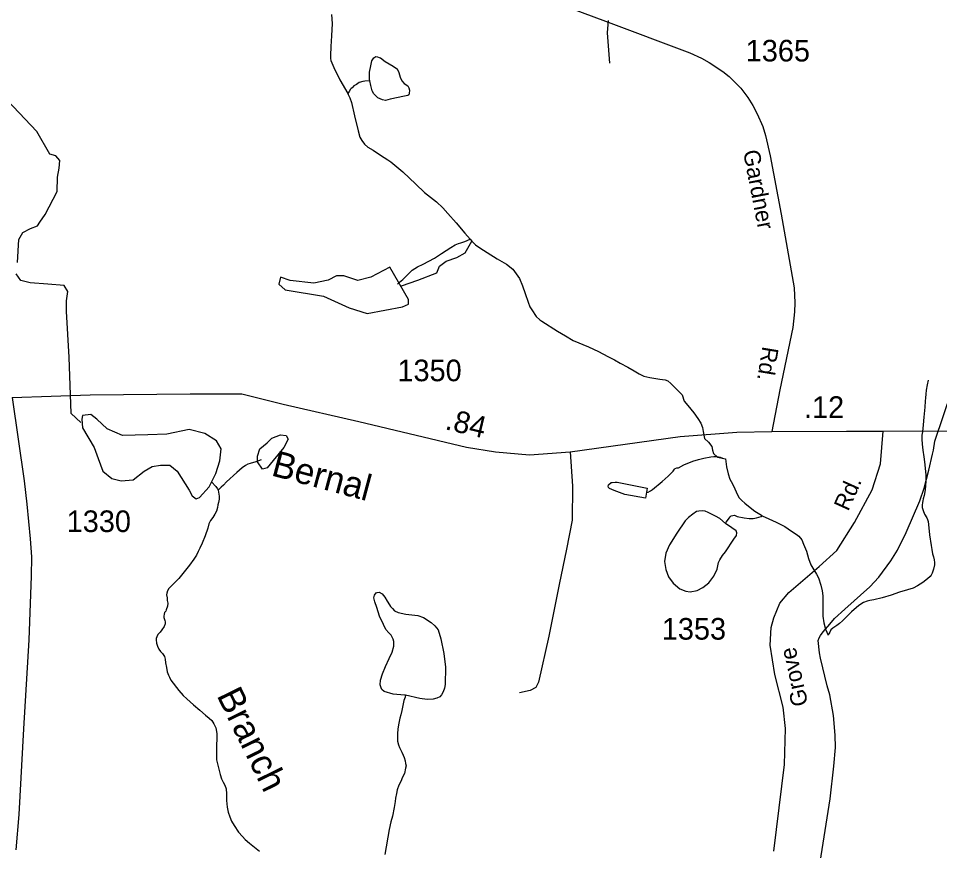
# Model space of a CAD drawing. Extents: x 2082433 to 2279600, y 546599 to 755198.
# Drawn here: x 2148448 to 2153778, y 616395 to 621207 of the extents above; entities that cross this region are included whole.
import ezdxf

# ---------------------------------------------------------------- set-up
doc = ezdxf.new("R2010")
doc.units = 0
for name, color, linetype in [('Exist Boundary Political Fire Districts', 7, 'Continuous'), ('Exist Hydrographic Creek Single Shore', 7, 'Continuous'), ('Exist Hydrographic Creek Single Shore Label', 7, 'Continuous'), ('Exist Hydrographic Misc Water Feature', 7, 'Continuous'), ('Exist Hydrographic Pond Over 1500 Sq Ft', 7, 'Continuous'), ('Exist Road Non-System Type 51', 7, 'Continuous'), ('Exist Road Secondary Mileage Hundredths English Label', 7, 'Continuous'), ('Exist Road Secondary Type 51 Attributed', 7, 'Continuous'), ('Exist Road Secondary Type 51 Label', 7, 'Continuous'), ('Exist Road Secondary Type 51 Number Label', 7, 'Continuous')]:
    doc.layers.add(name, color=color, linetype=linetype)

msp = doc.modelspace()

# ---------------------------------------------------------------- linework, layer by layer
at = {"layer": 'Exist Boundary Political Fire Districts'}
msp.add_lwpolyline([(2153087.7, 616327.6), (2153144.5, 616694.2), (2153165.6, 616882.9), (2153175, 616991.3), (2153173.8, 617061.5), (2153164.8, 617175.4), (2153143, 617295.8), (2153127.3, 617347.8), (2153088.3, 617506.9), (2153082.6, 617538.6), (2153075, 617609.9), (2153080.3, 617625.6), (2153088.3, 617638.8), (2153104.1, 617659.9), (2153142.2, 617704.7), (2153169.9, 617737.6), (2153229, 617790), (2153375.2, 617919.8), (2153426, 617975.8), (2153496.3, 618070.4), (2153534.9, 618132.7), (2153584.3, 618234), (2153663.7, 618416.5), (2153689.5, 618491.2), (2153715.5, 618594.3), (2153736.3, 618686.3), (2153741.8, 618710.3), (2153751.2, 618762.9), (2155677.9, 624465.5)], dxfattribs=at)
at = {"layer": 'Exist Hydrographic Creek Single Shore'}
for points in [[(2150258.8, 621229.1), (2150262.7, 621177), (2150259.2, 621107), (2150255.7, 621045), (2150253.9, 620993), (2150253.9, 620975.2), (2150255.9, 620963.1), (2150272.3, 620923.3), (2150308.8, 620851.3), (2150353.3, 620773.6)], [(2148442.2, 619795.2), (2148450.2, 619929.5), (2148473.1, 619969.9), (2148517.5, 619992.8), (2148559.3, 620007.6), (2148572.8, 620029.2), (2148602.4, 620073.6), (2148672.4, 620207), (2148673.8, 620289.2), (2148683.2, 620340.4), (2148687.3, 620384.8), (2148665.7, 620411.8), (2148629.3, 620421.2), (2148555.2, 620554), (2148313.3, 620804.9)], [(2150353.3, 620773.6), (2150357, 620767.8), (2150365, 620747.9), (2150375.3, 620720), (2150392.1, 620644), (2150414.4, 620556.3), (2150424.1, 620520.4), (2150434.3, 620500.2), (2150450.5, 620480.3), (2150469, 620462.5), (2150500.7, 620444.7), (2150543.2, 620416.8), (2150585, 620389), (2150603.1, 620377.3), (2150671.6, 620319.5), (2150747.6, 620247.9), (2150797.9, 620200.2), (2150866.4, 620146.9), (2150904.7, 620111.1), (2150933, 620079.2), (2150981.4, 620025.3), (2151031.4, 619965.8), (2151061.6, 619930)], [(2150664.8, 619660.7), (2150759.4, 619693.1), (2150868.9, 619735.4), (2150883.8, 619775.2), (2150923.6, 619802.6), (2150985.8, 619825), (2151033.1, 619852.4), (2151071.4, 619918)], [(2151061.6, 619930), (2151071.4, 619918), (2151093.5, 619898), (2151117.7, 619880.1), (2151160, 619852.7), (2151218.2, 619816.7), (2151272.4, 619785.4), (2151308.6, 619757.2), (2151328.5, 619729.4), (2151346.8, 619703.5), (2151365, 619659.8), (2151379.4, 619615.9), (2151397.8, 619566), (2151407.5, 619539.9), (2151425.9, 619510.3), (2151435.6, 619494.2), (2151443.8, 619484.1), (2151464.3, 619464.3), (2151476.2, 619456.5), (2151566.4, 619399), (2151614.4, 619371.1), (2151658.7, 619345.4), (2151746.8, 619308.1), (2151805.1, 619280.2), (2151859, 619252.6), (2151897.1, 619233), (2151929.5, 619213.2), (2151973.6, 619189.4), (2152011.4, 619169.5), (2152039.5, 619151.9), (2152067.3, 619138), (2152101.8, 619129.9), (2152159.6, 619120.3), (2152189.6, 619116.6), (2152206.2, 619110.5), (2152223.8, 619096.8), (2152248.4, 619070.8), (2152288, 619031.2), (2152300.1, 618993.3), (2152322.2, 618968.2), (2152355.4, 618926.9), (2152380, 618893.8), (2152396.6, 618866.1), (2152407.2, 618842), (2152409.2, 618818.9), (2152418.2, 618777.7), (2152440.8, 618757.1), (2152459.9, 618731.5), (2152464.5, 618710.9), (2152469.5, 618690.3), (2152492.1, 618669.7), (2152540, 618660.5)], [(2148810.1, 618870.1), (2148754.3, 618922.8), (2148741, 619247.6), (2148726, 619511.4), (2148726, 619573.6), (2148733.5, 619628.4), (2148713.6, 619663.2), (2148619, 619670.7), (2148517, 619678.1), (2148462.2, 619690.6), (2148434.8, 619730.4)], [(2149853, 618653.6), (2149821, 618643.4), (2149789.6, 618633.1), (2149775.3, 618629.2), (2149761.3, 618621.2), (2149743.1, 618608.9), (2149711.7, 618580.8), (2149652, 618526.6), (2149634, 618508.2), (2149622.3, 618496.2), (2149607.9, 618482.1), (2149604.5, 618478.2)], [(2152540, 618660.5), (2152544.3, 618614.9), (2152554.8, 618572.7), (2152564.6, 618542.8), (2152579.2, 618515.1), (2152593.1, 618487), (2152609.3, 618451.3), (2152619.3, 618435.2), (2152633.7, 618419.2), (2152651.3, 618403.2), (2152681.5, 618379.6), (2152709.8, 618357.9), (2152747.9, 618333.8), (2152751.8, 618330)], [(2149565.6, 618526.7), (2149590.3, 618500.2), (2149600.2, 618486.1), (2149604.5, 618478.2)], [(2149604.5, 618478.2), (2149606.1, 618468.3), (2149610.2, 618444.1), (2149610.6, 618426.2), (2149606.3, 618408.2), (2149602.8, 618394.1), (2149601, 618378.2), (2149594.6, 618358), (2149584.8, 618340), (2149573.3, 618321.9), (2149559.3, 618304.2), (2149549.1, 618284.2), (2149543.4, 618259.9), (2149529.6, 618215.8), (2149512.2, 618171.8), (2149498, 618143.9), (2149488.4, 618123.5), (2149478.1, 618103.5), (2149462.8, 618079.5), (2149438.4, 618045.4), (2149377.3, 617969.2), (2149337.3, 617928.9), (2149319.4, 617911), (2149311.6, 617896.7), (2149307.5, 617882.7), (2149305.3, 617874.6), (2149308, 617856.7), (2149309.8, 617840.6), (2149311.9, 617824.9), (2149310.2, 617809), (2149303.9, 617786.8), (2149300.4, 617778.8), (2149294.4, 617770.8), (2149292.2, 617762.6), (2149290.3, 617750.7), (2149290.1, 617742.6), (2149294.8, 617724.9), (2149296.5, 617716.9), (2149296.5, 617706.8), (2149290.9, 617690.6), (2149279, 617670.5), (2149269, 617658.7), (2149255.1, 617644.5), (2149248.9, 617630.4), (2149245.2, 617620.5), (2149245, 617614.4), (2149247.3, 617594.6), (2149253.6, 617576.6), (2149261.6, 617558.7), (2149269.4, 617546.6), (2149281.5, 617534.6), (2149285.6, 617528.8), (2149293.8, 617517), (2149297.9, 617501), (2149299.8, 617480.8), (2149304.1, 617453), (2149308.4, 617428.8), (2149316.2, 617409), (2149322.3, 617397.1), (2149330.7, 617381.2), (2149376.9, 617321.1), (2149400.8, 617291.6), (2149423, 617271.6), (2149461.5, 617237.7), (2149497, 617206), (2149529.8, 617178.4), (2149551.6, 617160.5), (2149568, 617146.6), (2149579.6, 617128.6), (2149589.9, 617104.8), (2149595.8, 617072.6), (2149596.3, 617038.5), (2149594.6, 617006.7), (2149594.6, 616980.8), (2149594.8, 616964.5), (2149595, 616944.6), (2149595, 616918.7), (2149597.3, 616904.5), (2149605.1, 616872.9), (2149615.3, 616834.9), (2149623.3, 616808.9), (2149633.6, 616791.2), (2149641.6, 616772.9), (2149649.8, 616751), (2149652, 616723.1), (2149652, 616685), (2149656.3, 616645), (2149662.5, 616617.3), (2149670.9, 616589.2), (2149680.5, 616565.5), (2149697.1, 616539.4), (2149721.3, 616501.7), (2149745.1, 616475.8), (2149759.5, 616459.9), (2149785.5, 616438.1), (2149803.8, 616421.9), (2149824.1, 616406.3), (2149844, 616392.4)], [(2152751.8, 618330), (2152789.9, 618314.1), (2152832.2, 618294.3), (2152882.4, 618268.9), (2152920.6, 618242.8), (2152948.7, 618225.2), (2152964.4, 618213.5), (2152980.8, 618191.2), (2152990.9, 618167.3), (2153007.3, 618125.5), (2153019.4, 618083.5), (2153033.3, 618047.7), (2153049.5, 618017.7), (2153066.1, 617993.8), (2153077.8, 617972.1), (2153090.3, 617930), (2153098.1, 617896), (2153102.4, 617868.2), (2153102.6, 617790.3), (2153103.3, 617750.1), (2153109.2, 617712.2), (2153117.6, 617676.1), (2153133.4, 617640.5)], [(2150688.4, 617292.7), (2150686.3, 617282.9), (2150678.7, 617262.5), (2150672.8, 617234.7), (2150667, 617204.7), (2150661.3, 617180.4), (2150655.4, 617160.6), (2150649.4, 617132.3), (2150643.9, 617098.7), (2150641.6, 617070.7), (2150641.8, 617046.7), (2150641.8, 617028.4), (2150648, 617006.4), (2150654.1, 616990.5), (2150666.4, 616964.7), (2150674.6, 616946.9), (2150680.8, 616932.9), (2150686.3, 616913), (2150688.8, 616898.9), (2150691, 616884.7), (2150688.8, 616870.9), (2150681.2, 616840.8), (2150669.1, 616814.7), (2150663.6, 616798.9), (2150649.4, 616772.6), (2150639.6, 616746.5), (2150635.9, 616724.8), (2150629.7, 616698.5), (2150628.1, 616678.5), (2150622.1, 616644.5), (2150612.5, 616594.5), (2150602.7, 616560.7), (2150592.6, 616516.4), (2150567.8, 616372.5)]]:
    msp.add_lwpolyline(points, dxfattribs=at)
at = {"layer": 'Exist Hydrographic Misc Water Feature'}
for points in [[(2150480.6, 620846.4), (2150478.8, 620856.4), (2150480.4, 620896.3), (2150486.4, 620932.3), (2150494, 620962.4), (2150503.8, 620978.3), (2150515.9, 620986.7), (2150525.8, 620984.8), (2150535.6, 620980.8), (2150543.8, 620978.8), (2150569.8, 620958.6), (2150616.2, 620930.9), (2150636.1, 620917.4), (2150640.4, 620915.1), (2150648.6, 620895.2), (2150656.2, 620867.3), (2150666.6, 620845.4), (2150680.4, 620831.6), (2150700.7, 620817.6), (2150706.6, 620805.7), (2150710.7, 620791.7), (2150709.1, 620773.7), (2150706.8, 620765.6), (2150701.1, 620761.6), (2150682.8, 620757.4), (2150599.2, 620739.3), (2150573.1, 620733.1), (2150555.1, 620737), (2150527.2, 620748.5), (2150504.8, 620770.5), (2150494.6, 620788.3), (2150487, 620818.3), (2150480.6, 620846.4)], [(2150480.6, 620846.4), (2150452.6, 620844.1), (2150440.7, 620842.3), (2150420.6, 620836), (2150404.8, 620825.8), (2150388.6, 620817.7), (2150378.5, 620805.8), (2150372.8, 620801.8), (2150368.7, 620797.6), (2150361.3, 620783.7), (2150353.3, 620773.6)], [(2150641, 619669.5), (2150652.9, 619681.5), (2150673, 619697.9), (2150692.9, 619718), (2150708.9, 619733.9), (2150726.3, 619750.3), (2150756.4, 619770.5), (2150790.3, 619786.5), (2150856.3, 619820.7), (2150895.9, 619847.2), (2150950, 619883.2), (2150975.8, 619897.6), (2150993.7, 619905.4), (2151007.6, 619909.8), (2151031.4, 619917.9), (2151061.6, 619930)], [(2153711.4, 619115.2), (2153705.5, 619089), (2153699.8, 619057), (2153697.7, 619035), (2153695.7, 619013), (2153693.6, 618993), (2153692.4, 618959.1), (2153686.4, 618901.3), (2153682.5, 618857.2), (2153678.8, 618816.8), (2153675.2, 618797.1), (2153675.4, 618773.2), (2153677.4, 618745.2), (2153681.5, 618711), (2153686, 618671), (2153689.9, 618643.2), (2153692.4, 618625), (2153698.5, 618565.2), (2153698.3, 618531.2), (2153694.8, 618481.5), (2153688.9, 618449.1), (2153683.2, 618429.3), (2153681.1, 618417), (2153679.1, 618407.2), (2153677.6, 618393.2), (2153677.2, 618379.1), (2153683.6, 618361.1), (2153691.4, 618341.2), (2153703.5, 618319.5), (2153707.8, 618309.6), (2153709.8, 618303.6), (2153711.7, 618297.2), (2153716.4, 618261.3), (2153720.3, 618221.7), (2153728.7, 618159.6), (2153732.8, 618135.5), (2153736.9, 618111.7), (2153742.8, 618093.8), (2153747.1, 618075.7), (2153749.4, 618061.6), (2153749.2, 618047.8), (2153743.4, 618021.5), (2153735.6, 617999.6), (2153729.7, 617987.5), (2153723.3, 617979.5), (2153707.3, 617965.7), (2153681.9, 617945.2), (2153650.1, 617925.3), (2153625.9, 617913.1), (2153591.9, 617902.9), (2153546.2, 617888.7), (2153498.6, 617872.4), (2153446.5, 617855.9), (2153398.3, 617845.8), (2153374.3, 617841.7), (2153358.3, 617837.6), (2153338.7, 617829.2), (2153310.6, 617811.2), (2153268.9, 617774.9), (2153243.1, 617750.8), (2153226.9, 617735), (2153215.6, 617722.9), (2153199.6, 617708.7), (2153183.6, 617696.5), (2153171.1, 617688.7), (2153159.7, 617680.7), (2153149.4, 617670.5), (2153143.7, 617658.4), (2153137.7, 617648.3), (2153133.4, 617640.5)], [(2152081.3, 618468.3), (2152091.3, 618468.4), (2152105.3, 618474.4), (2152117.6, 618482.3), (2152173.4, 618528.6), (2152206.8, 618560.8), (2152236.5, 618588.8), (2152244.5, 618601), (2152248.6, 618605.2), (2152258.4, 618609), (2152266.7, 618609), (2152298.2, 618625.3), (2152350.5, 618645.8), (2152382.3, 618656), (2152413.9, 618664.2), (2152454.1, 618672.3), (2152472.1, 618674.4), (2152490, 618674.6), (2152508, 618670.6), (2152521.9, 618664.5), (2152540, 618660.5)], [(2152081.3, 618468.3), (2152075.5, 618432.3), (2151957.6, 618453.3), (2151895.3, 618477), (2151867.4, 618488.9), (2151863.3, 618494.8), (2151861.3, 618502.8), (2151863.1, 618509), (2151877.1, 618523.1), (2151883, 618523.1), (2151901, 618525.2), (2151913.1, 618525.4), (2151979.2, 618511.7), (2152085.4, 618490.4), (2152081.3, 618468.3)], [(2152540.2, 618287), (2152506.2, 618314.4), (2152482.2, 618328.6), (2152439.9, 618350.4), (2152422.1, 618358), (2152405.7, 618360), (2152385.8, 618357.8), (2152371.8, 618355.8), (2152350.1, 618339.6), (2152326.1, 618321.4), (2152306.4, 618301.6), (2152256.8, 618231.3), (2152215.2, 618162.9), (2152193.7, 618115.1), (2152185.7, 618066.9), (2152193.7, 618021), (2152210.3, 617977.2), (2152236.1, 617941.2), (2152274.6, 617909.4), (2152310.5, 617895.5), (2152334.5, 617891.8), (2152374.7, 617898), (2152408.3, 617916.4), (2152442.4, 617942.4), (2152472.1, 617982.6), (2152492, 618022.6), (2152495.7, 618040.6), (2152499.6, 618060.8), (2152505.7, 618076.9), (2152521.5, 618100.8), (2152539.2, 618122.9), (2152586.9, 618195.1), (2152602.5, 618217.1), (2152604.4, 618233.1), (2152600.5, 618243.4), (2152576.3, 618260.8), (2152540.2, 618287)], [(2152540.2, 618287), (2152544.1, 618294.9), (2152550, 618302.9), (2152560.1, 618316.8), (2152566, 618324.8), (2152572.2, 618331.2), (2152581.8, 618333), (2152592.1, 618335.1), (2152606, 618327.3), (2152646.4, 618319.2), (2152676.3, 618315.5), (2152700.1, 618315.5), (2152718.2, 618319.7), (2152746.1, 618326), (2152751.8, 618330)]]:
    msp.add_lwpolyline(points, dxfattribs=at)
at = {"layer": 'Exist Hydrographic Pond Over 1500 Sq Ft'}
for points in [[(2149964.2, 619710.5), (2149954.2, 619670.7), (2149991.6, 619638.3), (2150213.1, 619601), (2150362.4, 619533.8), (2150466.9, 619501.4), (2150671, 619538.8), (2150705.9, 619553.7), (2150705.9, 619581.1), (2150596.4, 619767.7), (2150486.8, 619710.5), (2150412.2, 619690.6), (2150330.1, 619718), (2150287.7, 619718), (2150240.5, 619693.1), (2150158.3, 619675.7), (2150021.4, 619690.6)], [(2148866.6, 618916.6), (2148819.3, 618911.6), (2148814.4, 618889.2), (2148819.3, 618839.4), (2148886.5, 618724.9), (2148908.9, 618662.7), (2148936.3, 618588), (2148988.6, 618545.7), (2149043.3, 618533.3), (2149113, 618538.3), (2149175.2, 618588), (2149222.5, 618615.4), (2149269.8, 618622.9), (2149324.6, 618622.9), (2149366.9, 618588), (2149436.6, 618478.5), (2149454, 618446.2), (2149476.4, 618428.8), (2149496.3, 618436.2), (2149551.1, 618498.5), (2149590.9, 618575.6), (2149613.3, 618647.8), (2149620.7, 618717.5), (2149593.4, 618764.8), (2149526.2, 618807.1), (2149436.6, 618829.5), (2149307.2, 618802.1), (2149197.6, 618799.6), (2149050.8, 618794.6), (2148961.2, 618834.4), (2148901.5, 618889.2)], [(2149964.2, 618799.6), (2149996.6, 618794.6), (2150009, 618774.7), (2149984.1, 618724.9), (2149887, 618608), (2149859.7, 618600.5), (2149832.3, 618642.8), (2149832.3, 618675.2), (2149844.7, 618717.5), (2149887, 618752.3), (2149914.4, 618779.7)]]:
    msp.add_lwpolyline(points, close=True, dxfattribs=at)
msp.add_lwpolyline([(2150688.4, 617292.7), (2150682.4, 617292.8), (2150616.6, 617300.3), (2150564.5, 617313.9), (2150550.2, 617325.8), (2150546.5, 617335.7), (2150542.2, 617353.7), (2150544, 617379.8), (2150553.9, 617416.1), (2150571.3, 617460.1), (2150593.4, 617506.2), (2150610.9, 617542.1), (2150620.9, 617576.3), (2150620.9, 617604.3), (2150616.4, 617618.3), (2150604.3, 617640), (2150590.6, 617653.9), (2150574.2, 617673.8), (2150560.2, 617701.8), (2150538.1, 617749.8), (2150521.7, 617799.7), (2150509.6, 617833.6), (2150505.5, 617857.4), (2150509.4, 617871.3), (2150517.4, 617885.5), (2150523.1, 617887.5), (2150535, 617889.8), (2150553.2, 617879.7), (2150569, 617859.9), (2150581.5, 617837.7), (2150595.9, 617816.1), (2150601.8, 617805.9), (2150611.7, 617794.2), (2150623.8, 617782.2), (2150645.9, 617772.4), (2150689.8, 617762.6), (2150759.9, 617754.8), (2150791.9, 617743), (2150835.8, 617713.3), (2150858.1, 617693.7), (2150876.6, 617671.8), (2150892.4, 617619.5), (2150908.8, 617533.9), (2150919.7, 617456.1), (2150917.8, 617356.2), (2150914.1, 617334), (2150906.3, 617312.1), (2150896.3, 617295.8), (2150886.7, 617283.8), (2150868.8, 617275.6), (2150848.7, 617269.7), (2150812.4, 617269.5), (2150770.4, 617275.1), (2150688.4, 617292.7)], dxfattribs=at)
at = {"layer": 'Exist Road Non-System Type 51'}
for points in [[(2151859.8, 621195.3), (2151853.7, 621124.2), (2151868, 620947.5)], [(2151640.5, 618701.6), (2151654.7, 618502.6), (2151652.7, 618305.6), (2151620.2, 618137.1), (2151577.6, 617934), (2151516.6, 617635.5), (2151457.8, 617369.5), (2151441.5, 617337), (2151409, 617320.7), (2151348.1, 617306.5)]]:
    msp.add_lwpolyline(points, dxfattribs=at)
at = {"layer": 'Exist Road Secondary Type 51 Attributed'}
for points in [[(2151559.7, 621296.7), (2151845.4, 621191.7), (2152332, 621008.3), (2152401.1, 620977.6), (2152443.9, 620953), (2152523.7, 620900.2), (2152559.9, 620871.1), (2152627.8, 620803.2), (2152668, 620749.5), (2152697.6, 620703.7), (2152722.2, 620654.5), (2152755.4, 620582.1), (2152770.5, 620530.4), (2152797.1, 620411.8), (2152860.9, 620075.1), (2152936.8, 619649), (2152940.1, 619561.6), (2152938, 619510.3), (2152928.3, 619420.4), (2152852.9, 619060.1), (2152806.9, 618817.9)], [(2148412.4, 619015.4), (2148863.4, 619029.8), (2149441.7, 619036.1), (2149741.8, 619036.7), (2149980.4, 618976.3), (2150418.1, 618877), (2151040.7, 618728.3), (2151208.2, 618701.1), (2151404.9, 618684.3), (2151640.5, 618701.6), (2152276.6, 618789), (2152605.1, 618814.4), (2152806.9, 618817.9)], [(2148412.4, 619015.4), (2148481.1, 618533.1), (2148497.3, 618398.4), (2148516.8, 618198.4), (2148524.3, 618092.6), (2148521.6, 617980.8), (2148509.4, 617613), (2148477.1, 617098.4), (2148450.2, 616602.7), (2148434, 616399.2)], [(2153451.6, 618820.8), (2154087.5, 618822.5), (2154689.8, 618829.6), (2154890.3, 618826.1)], [(2152818.9, 616391.1), (2152880.1, 616892.7), (2152887.2, 617100), (2152872.1, 617224.1), (2152824.3, 617413.7), (2152797.7, 617582), (2152803, 617684.8), (2152818.9, 617741.5), (2152854.4, 617824.8), (2152906.7, 617886.9), (2153080.3, 618037.5), (2153184, 618129.6), (2153285.9, 618292.7), (2153388.7, 618480.5), (2153436.5, 618631.2), (2153451.6, 618820.8)], [(2152806.9, 618817.9), (2153239.6, 618820.2), (2153451.6, 618820.8)]]:
    msp.add_lwpolyline(points, dxfattribs=at)

# ---------------------------------------------------------------- texts
at = {"layer": 'Exist Hydrographic Creek Single Shore Label'}
for s, rotation, p in [('Bernal', 345.0279, (2149905.4, 618565.4)), ('Branch', 296.0838, (2149593.3, 617292.5))]:
    msp.add_text(s, height=150, rotation=rotation, dxfattribs=at).set_placement(p)
at = {"layer": 'Exist Road Secondary Mileage Hundredths English Label'}
msp.add_text('.12', height=125, dxfattribs=at).set_placement((2152993.3, 618897))
msp.add_text('.84', height=125, rotation=346.5691, dxfattribs=at).set_placement((2150911.7, 618832.2))
at = {"layer": 'Exist Road Secondary Type 51 Label'}
for s, rotation, p in [('Gardner', 280.9593, (2152640.4, 620437.8)), ('Rd.', 260.6931, (2152753.7, 619313.9)), ('Rd.', 65.6475, (2153248.9, 618353.2)), ('Grove', 102.4987, (2153018.2, 617240.1))]:
    msp.add_text(s, height=95, rotation=rotation, dxfattribs=at).set_placement(p)
at = {"layer": 'Exist Road Secondary Type 51 Number Label'}
for s, p in [('1365', (2152656.3, 620958.1)), ('1350', (2150641.1, 619109)), ('1330', (2148727.5, 618236.8)), ('1353', (2152170.7, 617614.7))]:
    msp.add_text(s, height=125, dxfattribs=at).set_placement(p)

doc.saveas('drawing.dxf')
